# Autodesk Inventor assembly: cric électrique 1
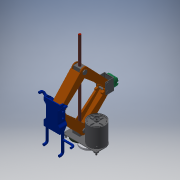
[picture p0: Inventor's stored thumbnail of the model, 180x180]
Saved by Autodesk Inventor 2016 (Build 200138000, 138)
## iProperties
Created: 2011-10
Part Number: cric électrique 1
Document SubType Name: Assembly
Designer: Bruno
Norme de conversion: STEP AP203
Nom du fichier: cric électrique 1.STEP
Préprocesseur: SolidWorks 2007
Postprocesseur: Build: 290c, Release: 11 - Date: Mon 03/13/2006
Unités envoyées: MILLIMETERS
Incertitude: 1e-05
Author: Bruno
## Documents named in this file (10)
- R:\SCIENCES INGENIEUR\Ressources communes\uhl\TSsi\1-Engrenages\Cric-Inventor\cric électrique 1.iam
- R:\SCIENCES INGENIEUR\Ressources communes\uhl\TSsi\1-Engrenages\Cric-Inventor\socle_D_faut.iam
- R:\SCIENCES INGENIEUR\Ressources communes\uhl\TSsi\1-Engrenages\Cric-Inventor\Support_D_faut.iam
- R:\SCIENCES INGENIEUR\Ressources communes\uhl\TSsi\1-Engrenages\Cric-Inventor\bras1_D_faut.ipt
- R:\SCIENCES INGENIEUR\Ressources communes\uhl\TSsi\1-Engrenages\Cric-Inventor\axe filet__mise en plan.iam
- R:\SCIENCES INGENIEUR\Ressources communes\uhl\TSsi\1-Engrenages\Cric-Inventor\bras2_D_faut.ipt
- R:\SCIENCES INGENIEUR\Ressources communes\uhl\TSsi\1-Engrenages\Cric-Inventor\Roue interm_diaire_mise en plan.iam
- R:\SCIENCES INGENIEUR\Ressources communes\uhl\TSsi\1-Engrenages\Cric-Inventor\rotor_mise en plan.iam
- R:\SCIENCES INGENIEUR\Ressources communes\uhl\TSsi\1-Engrenages\Cric-Inventor\moteur_D_faut.iam
- R:\SCIENCES INGENIEUR\Ressources communes\uhl\TSsi\1-Engrenages\Cric-Inventor\Ecrou_D_faut.iam
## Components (11 placed, 9 different names)
1. socle_D_faut:1 [sub-assembly] — Logement:1, Logement:2, Angle:1, Angle:2, Angle:3
2. Support_D_faut:1 [sub-assembly] — Logement:7, Logement:8, Angle:1, Angle:3
3. bras1_D_faut:1 — Logement:2, Logement:6, Logement:9
4. bras1_D_faut:2 — Logement:1, Logement:3
5. axe filet__mise en plan:1 [sub-assembly] — Logement:12, Plaquage:2, Angle:2
6. bras2_D_faut:1 — Logement:3, Logement:4, Logement:8
7. Roue interm_diaire_mise en plan:1 [sub-assembly] — Logement:11
8. rotor_mise en plan:1 [sub-assembly] — Logement:10
9. moteur_D_faut:1 [sub-assembly] — Logement:9, Logement:10, Logement:11, Logement:12
10. Ecrou_D_faut:1 [sub-assembly] — Logement:4, Plaquage:2
11. bras2_D_faut:2 — Logement:6, Logement:7
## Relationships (15: Insert 11, Angle 3, Mate 1)
- Logement:1 [Insert]: socle_D_faut:1 ↔ bras1_D_faut:2
- Logement:2 [Insert]: socle_D_faut:1 ↔ bras1_D_faut:1
- Logement:3 [Insert]: bras1_D_faut:2 ↔ bras2_D_faut:1
- Logement:4 [Insert]: bras2_D_faut:1 ↔ Ecrou_D_faut:1
- Logement:6 [Insert]: bras1_D_faut:1 ↔ bras2_D_faut:2
- Logement:7 [Insert]: Support_D_faut:1 ↔ bras2_D_faut:2
- Logement:8 [Insert]: Support_D_faut:1 ↔ bras2_D_faut:1
- Logement:9 [Insert]: bras1_D_faut:1 ↔ moteur_D_faut:1
- Logement:10 [Insert]: rotor_mise en plan:1 ↔ moteur_D_faut:1
- Logement:11 [Insert]: Roue interm_diaire_mise en plan:1 ↔ moteur_D_faut:1
- Logement:12 [Insert]: axe filet__mise en plan:1 ↔ moteur_D_faut:1
- Plaquage:2 [Mate]: axe filet__mise en plan:1 ↔ Ecrou_D_faut:1
- Angle:1: socle_D_faut:1 ↔ Support_D_faut:1
- Angle:2: socle_D_faut:1 ↔ axe filet__mise en plan:1
- Angle:3: socle_D_faut:1 ↔ Support_D_faut:1
